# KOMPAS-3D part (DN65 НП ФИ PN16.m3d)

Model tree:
1. Операция без истории:1

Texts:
  DN65 НП ФИ PN16
  133 1 134 1 135 1 136 0 50 1|SPDS|133 1 134 1 135 1 136 0 50 1
  125 1 126 1 127 1 128 0 50 1|SPDS|125 1 126 1 127 1 128 0 50 1
  129 1 130 1 131 1 132 0 50 1|SPDS|129 1 130 1 131 1 132 0 50 1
